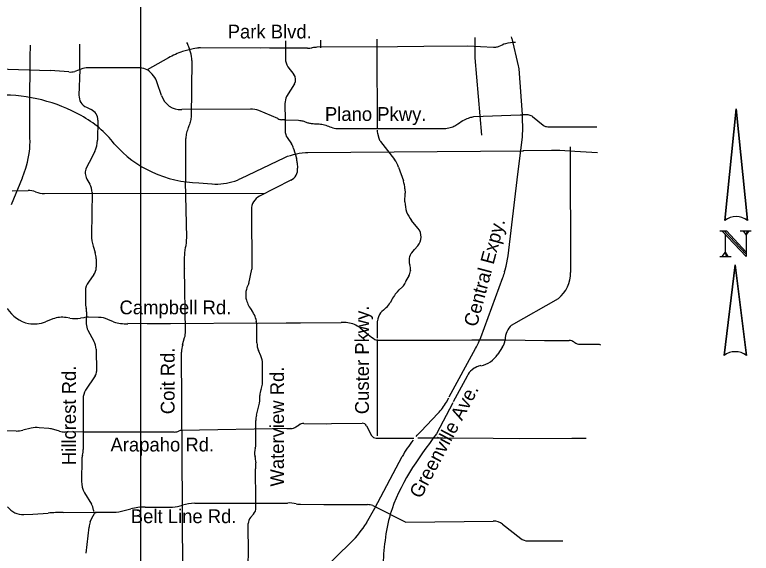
# Model space of a CAD drawing. Extents: x 105094 to 105814, y -291615 to -291123.
# Drawn here: x 105448.1 to 105512.8, y -291369.9 to -291322.6 of the extents above; entities that cross this region are included whole.
import ezdxf

# ---------------------------------------------------------------- set-up
doc = ezdxf.new("R2010")
doc.units = 0
doc.layers.add('G_BORDER', color=7, linetype='Continuous')
doc.layers.add('G_MAP', color=7, linetype='Continuous')

msp = doc.modelspace()

# ---------------------------------------------------------------- linework, layer by layer
at = {"layer": 'G_BORDER'}
msp.add_line((105459.139, -291158.398), (105459.139, -291578.398), dxfattribs=at)
at = {"layer": 'G_MAP'}
for p, q in [((105488.488, -291324.612), (105488.488, -291325.473)), ((105474.98, -291325.529), (105474.97, -291324.845)), ((105479.882, -291324.76), (105479.883, -291325.494)), ((105479.883, -291325.495), (105479.918, -291332.559)), ((105483.997, -291325.404), (105481.688, -291325.426)), ((105463.643, -291326.648), (105463.588, -291331.614)), ((105444.437, -291327.303), (105451.201, -291327.501)), ((105454.084, -291327.338), (105453.697, -291327.474)), ((105453.808, -291327.443), (105453.738, -291329.684)), ((105454.392, -291330.743), (105454.811, -291330.937)), ((105488.408, -291331.56), (105492.461, -291331.402)), ((105493.562, -291331.554), (105494.477, -291332.312)), ((105455.393, -291331.863), (105455.365, -291333.628)), ((105471.826, -291331.894), (105471.836, -291332.804)), ((105476.648, -291332.603), (105485.671, -291332.608)), ((105494.89, -291332.444), (105499.189, -291332.441)), ((105463.094, -291333.642), (105463.085, -291337.267)), ((105472.02, -291333.399), (105472.389, -291333.951)), ((105496.855, -291334.217), (105496.883, -291345.223)), ((105455.13, -291334.614), (105454.635, -291335.58)), ((105472.054, -291335.043), (105472.306, -291334.957)), ((105472.306, -291334.957), (105472.562, -291334.884)), ((105472.562, -291334.884), (105472.821, -291334.824)), ((105472.579, -291334.358), (105472.829, -291335.199)), ((105472.821, -291334.824), (105473.083, -291334.776)), ((105473.083, -291334.776), (105473.346, -291334.74)), ((105473.346, -291334.74), (105473.612, -291334.718)), ((105473.612, -291334.718), (105473.805, -291334.71)), ((105473.805, -291334.71), (105473.822, -291334.71)), ((105473.822, -291334.71), (105473.837, -291334.709)), ((105473.837, -291334.709), (105492.771, -291334.568)), ((105454.635, -291335.58), (105454.405, -291336.035)), ((105467.941, -291336.991), (105471.806, -291335.14)), ((105471.806, -291335.14), (105472.054, -291335.043)), ((105472.901, -291335.6), (105472.935, -291336.074)), ((105481.801, -291335.998), (105482.213, -291337.184)), ((105454.433, -291337.032), (105454.702, -291337.496)), ((105464.248, -291337.362), (105465.411, -291337.456)), ((105465.411, -291337.456), (105465.428, -291337.458)), ((105465.428, -291337.458), (105465.443, -291337.459)), ((105465.443, -291337.459), (105465.678, -291337.472)), ((105465.678, -291337.472), (105465.929, -291337.473)), ((105465.929, -291337.473), (105466.18, -291337.461)), ((105466.18, -291337.461), (105466.43, -291337.436)), ((105466.43, -291337.436), (105466.679, -291337.398)), ((105466.679, -291337.398), (105466.925, -291337.348)), ((105466.925, -291337.348), (105467.168, -291337.285)), ((105467.168, -291337.285), (105467.408, -291337.21)), ((105467.408, -291337.21), (105467.643, -291337.122)), ((105467.643, -291337.122), (105467.874, -291337.023)), ((105467.874, -291337.023), (105467.941, -291336.991)), ((105472.333, -291337.141), (105469.584, -291338.545)), ((105447.891, -291338.057), (105449.27, -291338.037)), ((105482.347, -291337.904), (105482.36, -291338.261)), ((105450.725, -291338.309), (105470.051, -291338.269)), ((105454.893, -291338.226), (105454.84, -291341.956)), ((105468.878, -291339.705), (105468.904, -291344.935)), ((105512.407, -291340.68), (105512.407, -291340.68)), ((105512.304, -291341.954), (105512.304, -291343.845)), ((105454.983, -291342.917), (105455.164, -291343.479)), ((105482.962, -291343.495), (105483.196, -291343.227)), ((105455.252, -291344.038), (105455.254, -291344.758)), ((105463.086, -291350.395), (105463.006, -291344.874)), ((105463.05, -291344.886), (105463.05, -291344.885)), ((105468.642, -291346.202), (105468.904, -291344.935)), ((105455.058, -291345.424), (105454.564, -291346.072)), ((105489.009, -291350.946), (105490.959, -291345.66)), ((105454.308, -291346.831), (105454.308, -291347.818)), ((105491.719, -291349.851), (105495.824, -291347.516)), ((105452.95, -291349.238), (105452.609, -291349.186)), ((105454.166, -291349.203), (105453.865, -291349.244)), ((105454.415, -291348.694), (105454.387, -291349.737)), ((105455.47, -291349.177), (105454.579, -291349.157)), ((105451.455, -291349.309), (105450.796, -291349.561)), ((105456.785, -291349.558), (105456.279, -291349.348)), ((105469.325, -291349.629), (105469.293, -291349.506)), ((105469.406, -291349.677), (105471.941, -291349.651)), ((105471.941, -291349.651), (105476.741, -291349.618)), ((105471.941, -291349.651), (105473.18, -291349.643)), ((105471.941, -291349.651), (105473.18, -291349.643)), ((105473.01, -291349.644), (105476.741, -291349.618)), ((105473.01, -291349.644), (105476.741, -291349.618)), ((105473.01, -291349.644), (105473.18, -291349.643)), ((105473.01, -291349.644), (105473.18, -291349.643)), ((105479.947, -291351.004), (105479.944, -291349.493)), ((105454.527, -291350.303), (105455.053, -291351.251)), ((105478.414, -291350.098), (105479.127, -291350.685)), ((105462.843, -291351.579), (105463.017, -291350.941)), ((105479.953, -291359.575), (105479.937, -291351.111)), ((105488.715, -291351.127), (105488.851, -291351.13)), ((105488.715, -291351.127), (105488.851, -291351.13)), ((105488.715, -291351.127), (105488.851, -291351.13)), ((105488.783, -291351.128), (105491.138, -291351.136)), ((105488.864, -291351.249), (105489.009, -291350.946)), ((105491.199, -291351.136), (105494.61, -291351.198)), ((105490.909, -291351.764), (105490.502, -291352.397)), ((105494.61, -291351.198), (105496.778, -291351.204)), ((105497.182, -291351.33), (105497.262, -291351.385)), ((105455.244, -291351.964), (105455.271, -291353.926)), ((105462.839, -291365.796), (105462.749, -291352.219)), ((105469.71, -291352.559), (105469.502, -291352.082)), ((105486.248, -291356.152), (105488.541, -291351.905)), ((105512.339, -291352.525), (105512.339, -291352.525)), ((105469.848, -291354.909), (105469.848, -291353.22)), ((105488.308, -291353.765), (105488.266, -291353.714)), ((105455.169, -291354.285), (105454.329, -291355.56)), ((105487.811, -291354.321), (105486.596, -291356.591)), ((105469.72, -291355.495), (105469.761, -291355.386)), ((105469.618, -291356.375), (105469.623, -291356.019)), ((105485.998, -291356.602), (105486.209, -291356.242)), ((105469.318, -291357.754), (105469.58, -291356.695)), ((105486.548, -291356.682), (105485.111, -291359.381)), ((105483.77, -291359.152), (105485.242, -291357.608)), ((105469.256, -291360.497), (105469.269, -291358.229)), ((105449.551, -291358.899), (105448.805, -291359.075)), ((105451.109, -291358.92), (105450.241, -291358.848)), ((105472.789, -291358.771), (105473.064, -291358.593)), ((105472.789, -291358.771), (105473.064, -291358.593)), ((105472.789, -291358.771), (105473.064, -291358.593)), ((105473.01, -291358.627), (105473.064, -291358.593)), ((105473.01, -291358.627), (105473.064, -291358.593)), ((105473.01, -291358.627), (105473.064, -291358.593)), ((105473.01, -291358.627), (105473.064, -291358.593)), ((105478.979, -291358.681), (105479.428, -291359.52)), ((105478.979, -291358.681), (105479.428, -291359.52)), ((105478.979, -291358.681), (105479.428, -291359.52)), ((105448.239, -291359.14), (105445.184, -291359.13)), ((105452.032, -291359.158), (105451.344, -291358.962)), ((105472.337, -291358.923), (105462.708, -291359.099)), ((105471.998, -291358.917), (105472.341, -291358.926)), ((105471.998, -291358.917), (105472.341, -291358.926)), ((105471.998, -291358.917), (105472.341, -291358.926)), ((105479.831, -291359.762), (105483.131, -291359.769)), ((105479.831, -291359.762), (105483.131, -291359.769)), ((105479.831, -291359.762), (105483.131, -291359.769)), ((105479.707, -291365.915), (105482.11, -291361.385)), ((105453.999, -291361.588), (105453.97, -291363.555)), ((105454.241, -291364.55), (105454.842, -291365.547)), ((105457.488, -291366.18), (105458.289, -291365.967)), ((105459.558, -291365.834), (105461.959, -291365.824)), ((105478.993, -291367.203), (105479.707, -291365.915)), ((105479.535, -291365.686), (105479.704, -291365.753)), ((105479.535, -291365.686), (105479.704, -291365.753)), ((105479.535, -291365.686), (105479.704, -291365.753)), ((105479.704, -291365.753), (105482.429, -291367.123)), ((105455.005, -291366.078), (105455.011, -291366.203)), ((105468.803, -291366.73), (105469.068, -291366.431)), ((105482.429, -291367.123), (105490.106, -291367.042)), ((105454.359, -291369.865), (105454.636, -291367.588)), ((105490.918, -291367.325), (105492.515, -291368.576)), ((105474.575, -291371.851), (105477.633, -291368.905))]:
    msp.add_line(p, q, dxfattribs=at)
for points in [[(105492.265, -291336.6), (105492.657, -291333.359), (105492.659, -291333.342), (105492.66, -291333.327), (105492.685, -291333.074), (105492.698, -291332.805), (105492.698, -291332.546), (105492.698, -291332.531), (105492.698, -291332.514), (105492.68, -291331.788), (105492.665, -291331.45), (105492.659, -291331.362), (105492.369, -291327.354), (105492.353, -291327.211), (105492.328, -291327.09), (105491.75, -291324.709), (105491.746, -291324.693), (105491.743, -291324.677), (105491.716, -291324.556)], [(105447.815, -291339.275), (105448.782, -291336.933), (105448.788, -291336.919), (105448.794, -291336.901), (105448.931, -291336.504), (105449.073, -291336.093), (105449.139, -291335.879), (105449.217, -291335.552), (105449.286, -291335.222), (105449.372, -291334.803), (105449.406, -291334.593), (105449.428, -291334.381), (105449.442, -291334.074), (105449.444, -291333.768), (105449.443, -291333.42), (105449.441, -291333.071), (105449.436, -291332.484), (105449.431, -291331.898), (105449.427, -291331.082), (105449.425, -291330.266), (105449.426, -291329.603), (105449.431, -291328.94), (105449.449, -291328.171), (105449.464, -291327.402), (105449.465, -291326.875), (105449.467, -291326.348), (105449.494, -291325.284)], [(105453.808, -291327.443), (105453.82, -291325.21)], [(105471.862, -291324.899), (105471.857, -291326.463)], [(105463.412, -291325.704), (105462.831, -291325.86)], [(105463.54, -291325.913), (105463.373, -291325.423)], [(105463.764, -291325.609), (105463.412, -291325.704)], [(105464.198, -291325.587), (105464.195, -291325.481)], [(105470.483, -291325.551), (105464.394, -291325.527)], [(105469.686, -291325.601), (105469.671, -291325.602)], [(105473.814, -291325.565), (105470.479, -291325.552)], [(105481.688, -291325.428), (105474.63, -291325.479)], [(105490.118, -291325.494), (105487.854, -291325.368), (105483.997, -291325.404)], [(105488.488, -291325.473), (105488.491, -291326.402), (105489.062, -291333.181)], [(105461.609, -291326.404), (105459.733, -291327.458)], [(105472.074, -291327.195), (105472.592, -291327.852)], [(105452.854, -291327.64), (105451.201, -291327.501)], [(105453.697, -291327.474), (105453.367, -291327.598)], [(105459.109, -291327.282), (105454.649, -291327.266)], [(105460.995, -291329.708), (105460.608, -291328.596)], [(105472.659, -291328.692), (105471.965, -291329.793)], [(105471.823, -291330.42), (105471.826, -291331.893)], [(105468.798, -291330.908), (105462.757, -291330.948)], [(105471.194, -291331.738), (105469.533, -291331.024)], [(105512.407, -291340.68), (105511.42, -291330.865), (105510.429, -291340.68)], [(105510.429, -291340.68), (105511.42, -291330.865), (105512.407, -291340.68)], [(105471.826, -291331.851), (105471.556, -291331.846)], [(105471.784, -291331.85), (105473.023, -291331.875)], [(105479.944, -291333.019), (105480.055, -291333.463)], [(105480.217, -291333.753), (105481.434, -291335.321)], [(105499.249, -291334.746), (105498.763, -291334.72), (105497.262, -291334.627), (105495.941, -291334.546), (105495.207, -291334.544), (105492.707, -291334.57)], [(105491.1, -291345.163), (105491.101, -291345.163), (105491.101, -291345.161), (105491.101, -291345.16), (105491.102, -291345.159), (105491.102, -291345.157), (105491.103, -291345.156), (105491.103, -291345.155), (105491.104, -291345.153), (105491.104, -291345.152), (105491.15, -291344.999), (105491.232, -291344.693), (105491.302, -291344.384), (105491.359, -291344.073), (105491.403, -291343.759), (105492.265, -291336.6)], [(105463.006, -291344.874), (105463.015, -291343.87), (105463.019, -291343.73), (105463.035, -291343.503), (105463.064, -291343.276), (105463.106, -291343.052), (105463.144, -291342.853), (105463.174, -291342.627), (105463.192, -291342.399), (105463.196, -291342.187), (105463.197, -291342.172), (105463.196, -291342.155), (105463.085, -291337.267)], [(105482.355, -291339.045), (105482.36, -291338.261)], [(105483.495, -291341.34), (105482.93, -291340.659)], [(105510.003, -291341.571), (105510.563, -291341.571)], [(105510.181, -291341.571), (105512.304, -291343.845)], [(105510.447, -291341.853), (105510.447, -291343.459), (105510.181, -291343.845)], [(105510.385, -291341.571), (105512.304, -291343.636)], [(105510.57, -291341.579), (105512.304, -291343.459)], [(105511.775, -291341.571), (105512.751, -291341.571)], [(105512.037, -291341.571), (105512.304, -291341.954)], [(105512.304, -291341.954), (105512.57, -291341.571)], [(105512.304, -291341.954), (105512.41, -291341.584)], [(105483.199, -291343.224), (105483.475, -291342.909)], [(105510.003, -291343.845), (105510.975, -291343.845)], [(105510.447, -291343.459), (105510.534, -291343.839)], [(105510.447, -291343.459), (105510.682, -291343.845)], [(105512.339, -291352.525), (105511.35, -291344.571), (105510.362, -291352.525)], [(105510.362, -291352.525), (105511.35, -291344.571), (105512.339, -291352.525)], [(105455.254, -291344.782), (105455.254, -291344.783), (105455.254, -291344.785), (105455.254, -291344.786), (105455.254, -291344.788), (105455.254, -291344.789), (105455.254, -291344.791), (105455.253, -291344.792), (105455.253, -291344.793), (105455.253, -291344.794)], [(105482.831, -291345.066), (105482.831, -291345.068), (105482.831, -291345.07), (105482.83, -291345.072), (105482.83, -291345.073), (105482.83, -291345.075), (105482.829, -291345.076), (105482.829, -291345.077), (105482.829, -291345.078)], [(105481.686, -291346.934), (105481.839, -291346.763), (105482.146, -291346.479)], [(105460.931, -291349.729), (105459.733, -291349.729), (105458.035, -291349.722)], [(105469.36, -291351.395), (105469.351, -291349.677), (105461.781, -291349.735)], [(105480.141, -291351.156), (105486.284, -291351.182), (105488.228, -291351.149)], [(105480.141, -291351.156), (105486.284, -291351.182), (105488.228, -291351.149)], [(105480.141, -291351.156), (105486.284, -291351.182), (105488.228, -291351.149)], [(105497.7, -291351.52), (105499.386, -291351.524), (105499.531, -291351.576)], [(105454.097, -291356.321), (105454.117, -291359.282), (105454.12, -291360.762)], [(105473.47, -291358.475), (105475.49, -291358.503), (105475.913, -291358.471), (105478.598, -291358.455)], [(105473.47, -291358.475), (105475.49, -291358.503), (105475.913, -291358.471), (105478.598, -291358.455)], [(105473.47, -291358.475), (105475.49, -291358.503), (105475.913, -291358.471), (105478.598, -291358.455)], [(105462.093, -291359.23), (105457.963, -291359.246), (105454.13, -291359.237), (105452.509, -291359.226)], [(105483.489, -291359.75), (105490.094, -291359.756), (105492.384, -291359.788), (105496.989, -291359.769), (105498.259, -291359.769)], [(105483.489, -291359.75), (105485.699, -291359.752)], [(105469.277, -291365.854), (105469.263, -291365.201), (105469.234, -291362.448)], [(105462.887, -291381.123), (105462.907, -291379.702), (105462.862, -291372.19), (105462.839, -291365.796)], [(105463.903, -291365.482), (105469.282, -291365.476), (105472.059, -291365.456)], [(105473.026, -291365.571), (105475.234, -291365.585), (105479.074, -291365.598)], [(105473.026, -291365.571), (105473.18, -291365.572)], [(105473.026, -291365.571), (105473.18, -291365.572)], [(105473.026, -291365.571), (105475.234, -291365.585), (105479.074, -291365.598)], [(105473.026, -291365.571), (105473.18, -291365.572)], [(105473.026, -291365.571), (105473.18, -291365.572)], [(105473.026, -291365.571), (105475.234, -291365.585), (105479.074, -291365.598)], [(105448.908, -291366.461), (105449.699, -291366.422), (105451.032, -291366.348)], [(105452.356, -291366.296), (105455.127, -291366.267), (105456.493, -291366.264)], [(105454.72, -291367.104), (105454.859, -291366.797), (105455.095, -291366.387)], [(105468.529, -291371.893), (105468.607, -291369.965), (105468.594, -291367.264)], [(105493.135, -291368.782), (105496.215, -291368.78)]]:
    msp.add_lwpolyline(points, dxfattribs=at)
for centre, radius, start, end in [((105454.353, -291329.043), 9.719, 21.86339, 24.2702), ((105464.489, -291331.225), 5.616, 107.17326, 120.90257), ((105461.393, -291326.588), 2.251, 358.47299, 17.45076), ((105464.375, -291327.841), 2.314, 89.51949, 105.30542), ((105473.772, -291323.462), 2.104, 271.15251, 282.0003), ((105474.643, -291327.776), 2.298, 90.32709, 100.88197), ((105473.679, -291326.321), 1.827, 184.45287, 208.57178), ((105452.987, -291326.115), 1.53, 265.0201, 284.56162), ((105454.57, -291328.88), 1.616, 87.19294, 107.48774), ((105459.068, -291328.617), 1.336, 60.18082, 88.23134), ((105458.617, -291329.218), 2.086, 17.34669, 56.28671), ((105472.019, -291328.32), 0.74, 329.8653, 39.24689), ((105446.989, -291343.88), 14.219, 60.75044, 90.80308), ((105454.865, -291329.719), 1.128, 178.20328, 245.19575), ((105462.676, -291329.191), 1.759, 197.08172, 272.62667), ((105473.187, -291330.398), 1.363, 153.66867, 180.92043), ((105454.39, -291331.847), 1.003, 359.09352, 65.19603), ((105468.863, -291332.899), 1.991, 70.332, 91.85259), ((105449.586, -291339.543), 9.167, 37.65261, 61.67154), ((105471.902, -291330.017), 1.861, 247.6381, 259.29656), ((105472.927, -291332.792), 1.092, 180.63245, 213.75725), ((105480.915, -291332.81), 0.993, 176.84675, 192.15534), ((105453.027, -291333.591), 2.338, 334.04791, 359.09363), ((105480.847, -291333.213), 0.83, 197.50833, 220.59498), ((105464.386, -291327.335), 10.028, 221.22585, 269.21197), ((105471.145, -291334.782), 1.496, 16.49276, 33.75722), ((105471.02, -291335.734), 1.886, 4.09482, 16.49274), ((105479.557, -291336.777), 2.375, 19.15277, 37.81178), ((105455.339, -291336.507), 1.047, 153.19003, 210.08365), ((105471.828, -291336.153), 1.11, 297.04687, 4.09483), ((105453.477, -291338.206), 1.416, 359.18183, 30.08363), ((105479.885, -291337.992), 2.464, 2.05843, 19.15254), ((105449.295, -291339.752), 1.716, 68.38553, 90.85992), ((105450.721, -291336.155), 2.153, 248.38549, 270.11736), ((105470.172, -291339.698), 1.295, 117.04706, 180.29097), ((105484.854, -291339.063), 2.499, 179.58824, 219.67861), ((105511.418, -291341.926), 1.59, 51.55799, 128.44201), ((105511.418, -291341.926), 1.59, 51.55799, 128.44201), ((105482.565, -291342.112), 1.209, 318.80601, 39.67856), ((105457.841, -291341.999), 3.002, 179.18183, 197.79866), ((105453.406, -291344.043), 1.846, 0.15847, 17.79864), ((105483.731, -291344.167), 1.021, 138.81089, 201.2098), ((105481.817, -291344.9), 1.027, 350.68981, 20.71217), ((105454.185, -291344.808), 1.068, 324.80256, 0.77522), ((105454.134, -291344.761), 1.119, 358.92778, 0.15847), ((105481.857, -291345.06), 0.972, 330.71302, 358.95043), ((105483.16, -291342.698), 8.343, 339.20615, 342.65174), ((105493.99, -291345.278), 2.894, 309.33721, 1.08401), ((105484.325, -291346.821), 2.068, 141.57368, 160.41777), ((105455.56, -291346.831), 1.252, 142.69844, 179.99527), ((105470.373, -291347.191), 1.994, 150.25934, 193.8477), ((105481.548, -291345.833), 0.88, 312.79352, 340.40795), ((105484.555, -291349.503), 3.851, 138.14962, 154.85372), ((105456.053, -291347.904), 1.747, 177.19617, 196.42222), ((105471.045, -291346.879), 2.724, 196.83608, 218.31346), ((105479.908, -291347.298), 1.293, 308.49573, 333.93139), ((105450.034, -291346.746), 3.06, 212.30227, 256.59239), ((105453.477, -291348.664), 0.938, 358.20459, 16.49639), ((105467.371, -291349.783), 1.958, 20.74824, 38.33883), ((105484.115, -291352.584), 5.463, 128.52434, 135.56161), ((105452.267, -291351.44), 2.28, 81.36071, 110.85652), ((105454.495, -291350.302), 1.147, 85.80296, 106.6852), ((105455.42, -291351.417), 2.241, 67.45538, 88.72314), ((105467.496, -291349.774), 1.839, 4.73158, 21.85907), ((105481.662, -291349.708), 1.732, 147.01862, 172.65578), ((105449.745, -291346.779), 2.973, 261.87381, 290.70129), ((105453.43, -291346.073), 3.2, 261.38239, 277.82289), ((105455.507, -291349.76), 1.12, 178.82238, 208.96181), ((105457.812, -291346.585), 3.146, 250.93561, 274.05226), ((105461.17, -291374.211), 24.483, 88.57143, 90.55923), ((105476.768, -291358.357), 8.739, 86.15585, 90.17642), ((105476.768, -291358.357), 8.739, 86.15585, 90.17642), ((105476.768, -291358.357), 8.739, 86.15585, 90.17642), ((105476.945, -291352.031), 2.428, 52.77711, 80.31187), ((105492.865, -291351.144), 1.728, 131.56303, 179.75525), ((105461.126, -291350.426), 1.96, 344.74832, 0.89969), ((105480.993, -291348.677), 2.741, 227.11179, 242.04665), ((105480.024, -291350.382), 0.783, 246.16027, 278.53868), ((105480.024, -291350.382), 0.783, 246.16027, 278.53868), ((105480.024, -291350.382), 0.783, 246.16027, 278.53868), ((105488.317, -291347.811), 3.34, 268.46239, 276.84533), ((105488.317, -291347.811), 3.34, 268.46239, 276.84533), ((105488.317, -291347.811), 3.34, 268.46239, 276.84533), ((105453.724, -291351.99), 1.521, 0.95918, 29.06438), ((105464.177, -291352.101), 1.432, 158.62189, 184.70443), ((105471.072, -291351.4), 1.711, 179.82392, 203.49158), ((105485.403, -291349.934), 3.706, 327.87326, 339.21326), ((105489.436, -291350.816), 1.751, 327.24979, 348.28632), ((105496.776, -291351.924), 0.719, 55.62386, 89.85671), ((105497.702, -291350.742), 0.778, 235.65026, 269.86465), ((105488.625, -291351.239), 2.205, 280.29578, 328.31079), ((105511.35, -291353.77), 1.59, 51.55799, 128.44201), ((105511.35, -291353.77), 1.59, 51.55799, 128.44201), ((105468.194, -291353.22), 1.654, 0, 23.57788), ((105489.314, -291355.033), 1.652, 100.28373, 129.67149), ((105489.314, -291355.033), 1.652, 107.97948, 129.67149), ((105489.314, -291355.033), 1.652, 125.52253, 129.67149), ((105454.654, -291353.946), 0.617, 326.62624, 1.79875), ((105489.077, -291354.879), 1.384, 126.20479, 156.22558), ((105489.077, -291354.879), 1.384, 126.20479, 156.22558), ((105489.077, -291354.879), 1.384, 126.20479, 156.22558), ((105468.491, -291354.909), 1.357, 339.43113, 359.99322), ((105455.503, -291356.333), 1.406, 146.62864, 179.50169), ((105471.162, -291356.034), 1.539, 159.49038, 179.4682), ((105468.851, -291356.444), 0.77, 341.01187, 5.1541), ((105481.303, -291353.856), 5.44, 316.39078, 329.67287), ((105470.417, -291358.106), 1.154, 162.24036, 186.09919), ((105450.058, -291361.047), 2.207, 85.24529, 103.28437), ((105472.269, -291357.971), 0.955, 274.13, 303.01357), ((105472.269, -291357.971), 0.955, 274.13, 303.01357), ((105472.269, -291357.971), 0.955, 274.13, 303.01357), ((105473.46, -291359.203), 0.728, 89.22005, 123.01897), ((105473.46, -291359.203), 0.728, 89.22005, 123.01897), ((105473.46, -291359.203), 0.728, 89.22005, 123.01897), ((105473.46, -291359.203), 0.728, 112.69348, 123.01897), ((105473.46, -291359.203), 0.728, 112.69348, 123.01897), ((105473.46, -291359.203), 0.728, 112.69348, 123.01897), ((105473.46, -291359.203), 0.728, 112.69348, 123.01897), ((105478.6, -291358.884), 0.429, 28.21612, 90.36198), ((105478.6, -291358.884), 0.429, 28.21612, 90.36198), ((105478.6, -291358.884), 0.429, 28.21612, 90.36198), ((105448.246, -291356.704), 2.436, 269.82515, 283.25933), ((105451.009, -291360.139), 1.224, 74.08536, 85.28758), ((105452.521, -291357.44), 1.787, 254.11348, 269.62349), ((105462.089, -291358.108), 1.122, 270.22266, 293.53862), ((105462.716, -291359.548), 0.449, 91.06723, 113.53142), ((105479.832, -291359.304), 0.458, 208.21635, 269.86667), ((105479.832, -291359.304), 0.458, 208.21635, 269.86667), ((105479.832, -291359.304), 0.458, 208.21635, 269.86667), ((105476.046, -291352.297), 10.328, 314.81033, 318.41045), ((105489.377, -291365.223), 8.218, 140.02688, 152.15765), ((105452.482, -291360.781), 1.639, 343.22076, 0.6889), ((105470.27, -291361.05), 1.126, 158.70172, 197.56656), ((105468.716, -291360.44), 0.542, 338.33721, 354.04442), ((105455.155, -291361.596), 1.156, 162.82416, 179.63164), ((105467.962, -291361.781), 1.295, 355.65773, 17.58648), ((105475.922, -291362.385), 6.688, 175.6589, 180.53806), ((105455.857, -291363.575), 1.888, 179.39677, 211.1001), ((105448.825, -291364.754), 1.709, 217.36211, 272.80393), ((105453.863, -291366.137), 1.143, 2.96309, 31.0918), ((105459.321, -291369.706), 3.879, 86.48936, 105.42534), ((105461.767, -291362.608), 3.222, 273.42765, 289.36144), ((105464.056, -291370.005), 4.525, 91.94699, 105.66152), ((105468.445, -291365.878), 0.833, 318.45423, 1.6725), ((105472.187, -291367.732), 2.279, 74.26913, 93.21203), ((105472.187, -291367.732), 2.279, 74.26913, 93.21203), ((105472.187, -291367.732), 2.279, 74.26913, 93.21203), ((105473.029, -291364.799), 0.772, 253.13477, 269.79907), ((105473.029, -291364.799), 0.772, 253.13477, 269.79907), ((105473.029, -291364.799), 0.772, 253.13477, 269.79907), ((105473.029, -291364.799), 0.772, 264.76721, 269.79907), ((105473.029, -291364.799), 0.772, 264.76721, 269.79907), ((105473.029, -291364.799), 0.772, 264.76721, 269.79907), ((105473.029, -291364.799), 0.772, 264.76721, 269.79907), ((105479.07, -291366.86), 1.262, 68.40519, 89.81611), ((105479.07, -291366.86), 1.262, 68.40519, 89.81611), ((105479.07, -291366.86), 1.262, 68.40519, 89.81611), ((105452.092, -291376.51), 10.217, 88.51802, 95.95443), ((105455.216, -291366.456), 0.139, 74.32355, 150.32531), ((105456.647, -291362.148), 4.118, 267.86629, 281.78772), ((105457.012, -291367.751), 2.382, 164.2398, 176.0892), ((105469.429, -291367.283), 0.835, 138.49816, 178.67541), ((105469.374, -291360.912), 11.494, 315.94033, 326.81552), ((105490.119, -291368.308), 1.267, 50.91363, 90.60754), ((105493.135, -291367.75), 1.033, 233.1082, 270.00811)]:
    msp.add_arc(centre, radius, start, end, dxfattribs=at)
for points in [[(105492.071, -291325.067), (105491.166, -291325.162), (105490.608, -291325.42)], [(105490.608, -291325.42), (105490.314, -291325.491), (105490.118, -291325.494)], [(105463.588, -291331.614), (105463.504, -291332.036), (105463.355, -291332.459)], [(105485.671, -291332.608), (105486.206, -291332.553), (105486.654, -291332.405), (105487.006, -291332.189), (105487.567, -291331.831), (105488.063, -291331.644), (105488.408, -291331.56)], [(105492.461, -291331.402), (105493.026, -291331.374), (105493.407, -291331.457), (105493.562, -291331.554)], [(105473.023, -291331.875), (105473.391, -291331.94), (105473.681, -291332.043), (105473.968, -291332.133), (105474.287, -291332.172), (105474.813, -291332.198), (105475.297, -291332.278), (105475.764, -291332.449), (105476.277, -291332.591), (105476.648, -291332.603)], [(105494.477, -291332.312), (105494.68, -291332.415), (105494.89, -291332.444)], [(105463.355, -291332.459), (105463.336, -291332.51), (105463.188, -291332.987), (105463.107, -291333.439), (105463.094, -291333.642)], [(105485.111, -291359.381), (105481.067, -291366.438), (105480.399, -291371.098), (105480.317, -291372.658)]]:
    msp.add_spline(points, degree=3, dxfattribs=at)

# ---------------------------------------------------------------- texts
for s, height, p in [('Park Blvd.', 1.2111, (105466.794, -291324.703)), ('Plano Pkwy.', 1.21107, (105475.331, -291331.938)), ('Campbell Rd.', 1.21107, (105457.3, -291348.901)), ('Arapaho Rd.', 1.21107, (105456.509, -291360.937)), ('Belt Line Rd.', 1.21107, (105458.293, -291367.221))]:
    msp.add_text(s, height=height, dxfattribs=at).set_placement(p)
for s, height, rotation, p in [('Central Expy.', 1.21107, 75.02956, (105488.66, -291350.071)), ('Custer Pkwy.', 1.21107, 90, (105479.189, -291357.667)), ('Coit Rd.', 1.2111, 90, (105462.133, -291357.667)), ('Hillcrest Rd.', 1.21107, 90, (105453.468, -291362.13)), ('Waterview Rd.', 1.21107, 90, (105471.735, -291364.016)), ('Greenville Ave.', 1.21107, 62.18035, (105483.745, -291365.147))]:
    msp.add_text(s, height=height, rotation=rotation, dxfattribs=at).set_placement(p)

doc.saveas('drawing.dxf')
